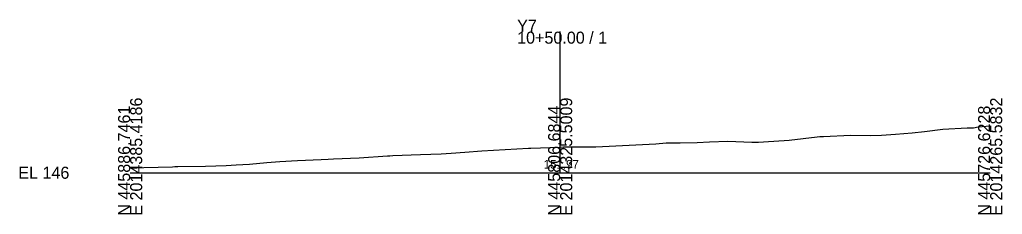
# Model space of a CAD drawing. Extents: x -26 to 203, y -10 to 7527.
# Drawn here: x -25.7 to 202.8, y 990.3 to 1035.6 of the extents above; entities that cross this region are included whole.
import ezdxf

# ---------------------------------------------------------------- set-up
doc = ezdxf.new("R2010")
doc.units = 0
for name, color, linetype in [('Exist Cross Section Cell', 7, 'Continuous'), ('Exist XS Center Line Elevation Label', 7, 'Continuous'), ('Exist XS Ground Line', 7, 'Continuous')]:
    doc.layers.add(name, color=color, linetype=linetype)

msp = doc.modelspace()

# ---------------------------------------------------------------- linework, layer by layer
at = {"layer": 'Exist Cross Section Cell'}
for p, q in [((100, 1000), (100, 1032.83)), ((0, 1000), (100, 1000)), ((100, 1000), (200, 1000))]:
    msp.add_line(p, q, dxfattribs=at)
at = {"layer": 'Exist XS Ground Line'}
msp.add_lwpolyline([(0, 1001.07), (3.22, 1001.18), (9.85, 1001.4), (10.37, 1001.41), (11.06, 1001.42), (17.51, 1001.49), (22.35, 1001.65), (24.66, 1001.81), (27.75, 1002.01), (31.8, 1002.37), (34.84, 1002.58), (38.95, 1002.82), (44.44, 1003.11), (46.09, 1003.15), (47.33, 1003.23), (53.24, 1003.5), (59.82, 1003.9), (60.38, 1003.94), (61.13, 1003.97), (67.53, 1004.24), (72.31, 1004.43), (74.67, 1004.55), (77.82, 1004.76), (81.82, 1005.13), (92.68, 1005.72), (93.15, 1005.74), (100, 1005.97), (100.78, 1005.99), (103.19, 1006), (107.46, 1006.02), (108.34, 1006.05), (122.28, 1006.75), (124.68, 1006.94), (127.9, 1006.98), (131.83, 1007.06), (134.77, 1007.19), (138.97, 1007.37), (144.59, 1007.09), (146.12, 1007.09), (147.26, 1007.16), (153.26, 1007.59), (159.76, 1008.34), (160.41, 1008.43), (161.28, 1008.46), (167.55, 1008.74), (172.25, 1008.67), (174.7, 1008.74), (177.97, 1009), (181.84, 1009.31), (184.74, 1009.63), (188.99, 1010.16), (194.66, 1010.44), (196.13, 1010.44), (197.23, 1010.7), (200, 1010.94)], dxfattribs=at)

# ---------------------------------------------------------------- texts
at = {"layer": 'Exist Cross Section Cell'}
for s, p in [('Y7', (90, 1032.83)), ('10+50.00 / 1', (90, 1030.03)), ('EL 146', (-26, 998.6))]:
    msp.add_text(s, height=2.8, dxfattribs=at).set_placement(p)
for s, p in [('E 2014385.4186', (2.8, 990)), ('E 2014325.5009', (102.8, 990)), ('E 2014265.5832', (202.8, 990)), ('N 445886.7461', (0, 990)), ('N 445806.6844', (100, 990)), ('N 445726.6228', (200, 990))]:
    msp.add_text(s, height=2.8, rotation=90, dxfattribs=at).set_placement(p)
at = {"layer": 'Exist XS Center Line Elevation Label'}
msp.add_text('151.97', height=2, dxfattribs=at).set_placement((96.18, 1000.97))

doc.saveas('drawing.dxf')
